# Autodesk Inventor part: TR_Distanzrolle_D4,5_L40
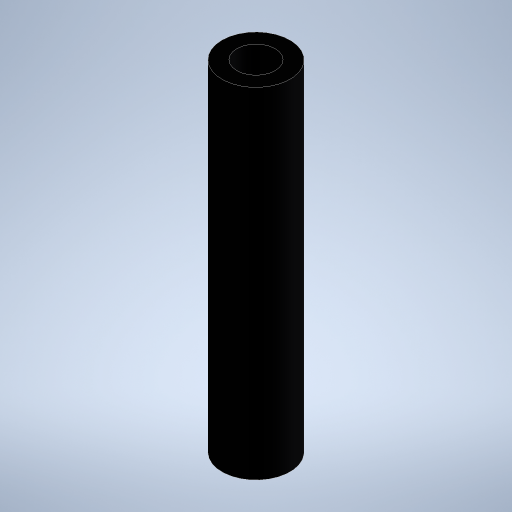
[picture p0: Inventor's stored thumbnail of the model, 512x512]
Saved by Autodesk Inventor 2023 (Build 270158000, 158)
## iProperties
Created: 2023-11
Part Number: TR_Distanzrolle_D4,5_L40
Material: PC/ABS-Kunststoff
Document SubType Name: Modeling
Designer: Admin
Density: 0.357273 g/cm^3
Appearance: Glatt - Schwarz
Author: Admin
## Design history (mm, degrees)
sketch "Skizze1"
  geometry: C1 r 2.25 at (0, 0); C2 r 4 at (0, 0); 1 further point
  constraints: 2 centre point, 2 coincident
  dimensions: "d0" = 4.5 diameter of C1; "d1" = 8 diameter of C2
extrude "Extrusion1" new body sketch "Skizze1" distance "d2" = 40; taper "d3" = 0 deg
node "Volumenkörper1"
